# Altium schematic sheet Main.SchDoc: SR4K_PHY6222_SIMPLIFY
size A4; DrawnBy: emmovo@outlook.com; Revision: V1.2; SheetNumber: 1; SheetTotal: 5
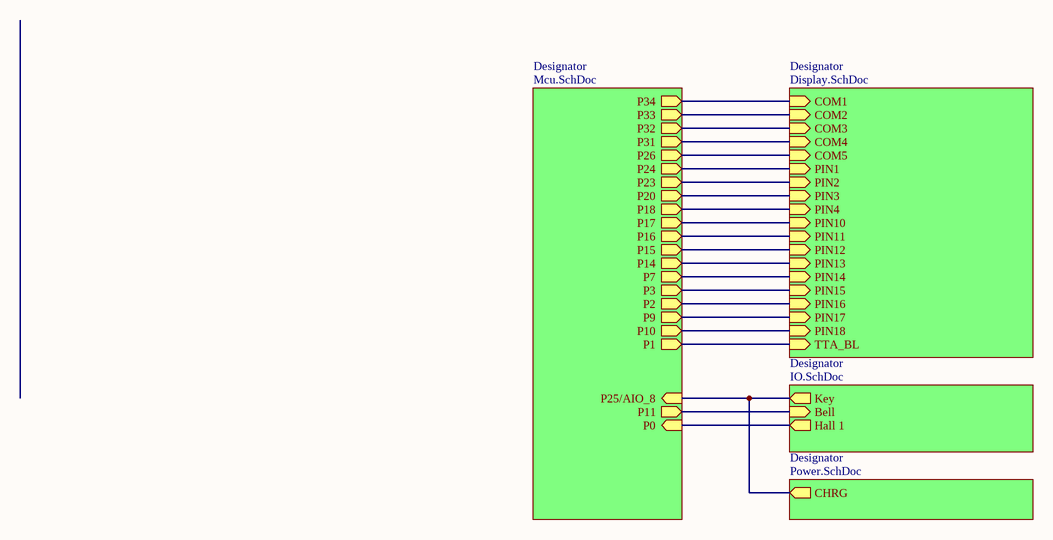
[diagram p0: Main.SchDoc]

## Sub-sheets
Designator = Display.SchDoc: COM1 (in), TTA_BL (in), COM2 (in), COM3 (in), COM4 (in), COM5 (in), PIN1 (in), PIN2 (in), PIN3 (in), PIN4 (in), PIN10 (in), PIN11 (in), PIN12 (in), PIN13 (in), PIN14 (in), PIN15 (in), PIN16 (in), PIN17 (in), PIN18 (in)
Designator = Power.SchDoc: CHRG (out)
Designator = IO.SchDoc: Key (out), Hall 1 (out), Bell (in)
Designator = Mcu.SchDoc: P34 (out), P33 (out), P32 (out), P31 (out), P26 (out), P25/AIO_8 (in), P24 (out), P23 (out), P0 (in), P11 (out), P14 (out), P15 (out), P20 (out), P18 (out), P17 (out), P16 (out), P7 (out), P3 (out), P2 (out), P1 (out), P9 (out), P10 (out)

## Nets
(unnamed): sheet Designator/COM1, sheet Designator/P34
(unnamed): sheet Designator/TTA_BL, sheet Designator/P1  [a separate net that carries the same name]
(unnamed): sheet Designator/COM2, sheet Designator/P33  [a separate net that carries the same name]
(unnamed): sheet Designator/COM3, sheet Designator/P32  [a separate net that carries the same name]
(unnamed): sheet Designator/COM4, sheet Designator/P31  [a separate net that carries the same name]
(unnamed): sheet Designator/COM5, sheet Designator/P26  [a separate net that carries the same name]
(unnamed): sheet Designator/PIN1, sheet Designator/P24  [a separate net that carries the same name]
(unnamed): sheet Designator/PIN2, sheet Designator/P23  [a separate net that carries the same name]
(unnamed): sheet Designator/PIN3, sheet Designator/P20  [a separate net that carries the same name]
(unnamed): sheet Designator/PIN4, sheet Designator/P18  [a separate net that carries the same name]
(unnamed): sheet Designator/PIN10, sheet Designator/P17  [a separate net that carries the same name]
(unnamed): sheet Designator/PIN11, sheet Designator/P16  [a separate net that carries the same name]
(unnamed): sheet Designator/PIN12, sheet Designator/P15  [a separate net that carries the same name]
(unnamed): sheet Designator/PIN13, sheet Designator/P14  [a separate net that carries the same name]
(unnamed): sheet Designator/PIN14, sheet Designator/P7  [a separate net that carries the same name]
(unnamed): sheet Designator/PIN15, sheet Designator/P3  [a separate net that carries the same name]
(unnamed): sheet Designator/PIN16, sheet Designator/P2  [a separate net that carries the same name]
(unnamed): sheet Designator/PIN17, sheet Designator/P9  [a separate net that carries the same name]
(unnamed): sheet Designator/PIN18, sheet Designator/P10  [a separate net that carries the same name]
(unnamed): sheet Designator/CHRG, sheet Designator/Key, sheet Designator/P25/AIO_8  [a separate net that carries the same name]
(unnamed): sheet Designator/Hall 1, sheet Designator/P0  [a separate net that carries the same name]
(unnamed): sheet Designator/Bell, sheet Designator/P11  [a separate net that carries the same name]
